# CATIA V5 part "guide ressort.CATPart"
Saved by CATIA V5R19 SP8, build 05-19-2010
Part number: CE6 Guide ressort
Revision: ANY
Definition: UNKNOWN
Nomenclature: guide ressort
Source: Unknown
Bounding box of the stored display mesh (mm): x -5.5 to 5.5, y -27 to 0.115, z 0 to 1.5
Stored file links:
  D:\Documents\1_Travail\1 - ac-limoges.fr\ac-limoges.fr\Emmanuel Maynard - STI2D_Turgot\2 -2I2D\2_SEQUENCE_Serrure_Biométrique\5-Spé_ITEC\Serrure_Bio_Eleve\guide ressort.CATPart
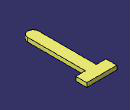
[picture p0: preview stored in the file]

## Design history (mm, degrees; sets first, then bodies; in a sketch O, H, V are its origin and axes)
Body1 "Extrusion3" (main body)
  Solid1: solid without history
